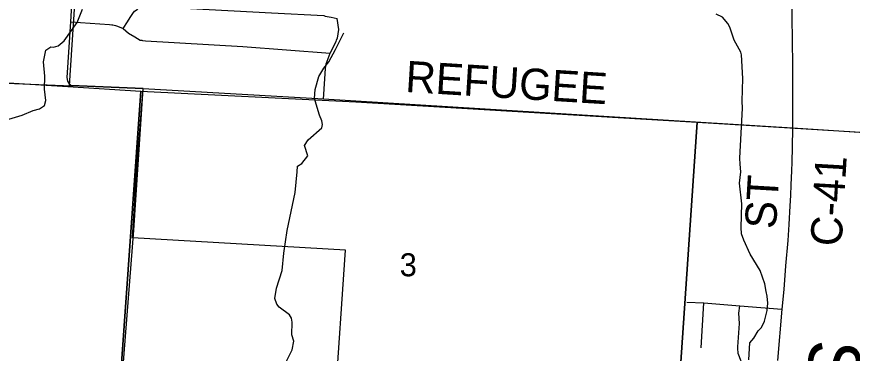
# Model space of a CAD drawing. Extents: x 0 to 34, y 0 to 26.1.
# Drawn here: x 26.701 to 28.22, y 20.153 to 20.765 of the extents above; entities that cross this region are included whole.
import ezdxf

# ---------------------------------------------------------------- set-up
doc = ezdxf.new("R2010")
doc.units = 0
for name, color, linetype in [('GM_X_City_Street', 7, 'Continuous'), ('GM_X_County_Road', 7, 'Continuous'), ('GM_X_County_Road_Text', 7, 'Continuous'), ('GM_X_Minor_River', 7, 'Continuous'), ('GM_X_Minor_River_Text', 7, 'Continuous'), ('GM_X_Section', 7, 'Continuous'), ('GM_X_Section_Text', 7, 'Continuous'), ('GM_X_Township_Road', 7, 'Continuous'), ('GM_X_Township_Road_Text', 7, 'Continuous'), ('SC_Scratch1', 7, 'Continuous')]:
    doc.layers.add(name, color=color, linetype=linetype)

msp = doc.modelspace()

# ---------------------------------------------------------------- linework, layer by layer
at = {"layer": 'GM_X_City_Street'}
for points in [[(26.8945, 20.7439), (26.902, 20.7562), (26.9069, 20.7638), (26.9121, 20.7711), (26.9152, 20.7752), (26.9197, 20.7787), (26.9227, 20.7814), (26.9258, 20.7829), (26.9307, 20.7852), (26.9356, 20.7867), (26.9424, 20.7871), (26.9516, 20.7872), (27.0169, 20.7802), (27.1642, 20.7721), (27.2591, 20.7676), (27.2618, 20.7665), (27.2728, 20.7646), (27.2834, 20.762)], [(26.7991, 20.7558), (26.8697, 20.7511), (26.8735, 20.7508), (26.8754, 20.7508), (26.8781, 20.75), (26.8807, 20.7496), (26.8842, 20.7481), (26.8945, 20.7439), (26.9038, 20.7351), (26.9153, 20.7284), (26.9253, 20.7229), (26.9283, 20.7225), (26.9298, 20.7221), (26.9348, 20.7214), (27.1121, 20.7108), (27.2707, 20.6992)], [(27.2587, 20.6151), (27.261, 20.652), (27.2622, 20.671), (27.2635, 20.6796), (27.2707, 20.6992), (27.2712, 20.7004), (27.2813, 20.7202), (27.2825, 20.7225), (27.284, 20.7267), (27.2847, 20.7301), (27.2854, 20.7343), (27.2862, 20.7419), (27.2834, 20.762)], [(26.6823, 20.6445), (26.8002, 20.6395)]]:
    msp.add_lwpolyline(points, dxfattribs=at)
at = {"layer": 'GM_X_County_Road'}
for points in [[(28.1081, 20.9), (28.1083, 20.8906), (28.1095, 20.8063), (28.11, 20.7606), (28.1105, 20.7257), (28.1113, 20.6737), (28.1112, 20.6162), (28.111, 20.5622)], [(28.111, 20.5622), (28.1107, 20.5278), (28.1099, 20.5008), (28.1095, 20.4847), (28.108, 20.4593), (28.1073, 20.4397), (28.1064, 20.421), (28.1045, 20.3872), (28.1026, 20.358), (28.0984, 20.3122), (28.0952, 20.2689), (28.0916, 20.233), (28.0838, 20.1395)]]:
    msp.add_lwpolyline(points, dxfattribs=at)
at = {"layer": 'GM_X_Minor_River'}
for points in [[(26.6868, 20.579), (26.7107, 20.5862), (26.7307, 20.5949), (26.7421, 20.5976), (26.7516, 20.604), (26.7535, 20.6127), (26.7527, 20.6234), (26.7516, 20.6332), (26.752, 20.6571), (26.7498, 20.6829), (26.7536, 20.7046), (26.7627, 20.7102), (26.768, 20.7099), (26.7759, 20.7121), (26.7869, 20.7216), (26.8108, 20.7546), (26.8203, 20.7789)], [(28.0319, 20.1409), (28.0338, 20.172), (28.0411, 20.1804), (28.0487, 20.1936), (28.0547, 20.1997), (28.0604, 20.2111), (28.0654, 20.2304), (28.0662, 20.2441), (28.0651, 20.2566), (28.0632, 20.2653), (28.0609, 20.279), (28.0523, 20.3037), (28.0342, 20.3333), (28.0225, 20.3584), (28.0187, 20.3702), (28.018, 20.3816), (28.0188, 20.4245), (28.0151, 20.4624), (28.0171, 20.4829), (28.0163, 20.497), (28.0156, 20.5076), (28.0203, 20.5987), (28.02, 20.6116), (28.0208, 20.653), (28.0182, 20.6958), (28.0171, 20.7008), (28.0054, 20.7224), (27.9971, 20.7464), (27.9937, 20.7532), (27.9839, 20.7642), (27.9722, 20.77)], [(27.1844, 20.1253), (27.2015, 20.1591), (27.2045, 20.1746), (27.2012, 20.1864), (27.2016, 20.2092), (27.2005, 20.2168), (27.1967, 20.2229), (27.1778, 20.2369), (27.1736, 20.2419), (27.1702, 20.2525), (27.1729, 20.2711), (27.1832, 20.3033), (27.1863, 20.3348), (27.1928, 20.3762), (27.207, 20.4456), (27.2105, 20.4832), (27.2112, 20.4931), (27.2192, 20.4984), (27.2298, 20.512), (27.2242, 20.531), (27.2307, 20.5412), (27.2553, 20.5628), (27.2565, 20.5689), (27.2557, 20.5757), (27.2516, 20.586), (27.2486, 20.5943), (27.2425, 20.6164), (27.2437, 20.6331), (27.2498, 20.6562), (27.2593, 20.6717), (27.2684, 20.6831), (27.2802, 20.7058), (27.2954, 20.7362)]]:
    msp.add_lwpolyline(points, dxfattribs=at)
at = {"layer": 'GM_X_Section'}
for points in [[(25.926, 20.6906), (26.2619, 20.6708), (26.7939, 20.6382), (26.9267, 20.63), (26.8884, 20.0918), (26.3915, 20.1255), (26.3885, 20.1257), (25.892, 20.1588)], [(26.9267, 20.63), (27.3172, 20.6101), (27.8347, 20.5796), (27.9376, 20.5735), (27.9001, 20.0205), (27.4021, 20.0547), (26.8884, 20.0918)], [(27.9376, 20.5735), (28.3638, 20.5476), (28.9502, 20.5089), (28.9104, 19.9472), (28.4191, 19.9828), (27.9001, 20.0205)]]:
    msp.add_lwpolyline(points, close=True, dxfattribs=at)
at = {"layer": 'GM_X_Township_Road'}
for p, q in [((26.9307, 20.6339), (26.8002, 20.6395)), ((27.9451, 20.1628), (27.9502, 20.2444))]:
    msp.add_line(p, q, dxfattribs=at)
for points in [[(26.8002, 20.6395), (26.7966, 20.6429), (26.7937, 20.6477), (26.7927, 20.6547), (26.7991, 20.7558), (26.8075, 20.9)], [(26.8913, 20.0905), (26.9136, 20.3771), (26.9307, 20.6339)], [(28.111, 20.5622), (27.2587, 20.6151), (26.9307, 20.6339)], [(29.9005, 20.446), (29.3177, 20.4844), (28.111, 20.5622)], [(27.9189, 20.2461), (27.9502, 20.2444), (28.0154, 20.2392), (28.0916, 20.233)], [(28.0186, 20.0892), (28.021, 20.1217), (28.0201, 20.1316), (28.0167, 20.1416), (28.0136, 20.1492), (28.0126, 20.1524), (28.0122, 20.1553), (28.0118, 20.1592), (28.0119, 20.1643), (28.0126, 20.1731), (28.015, 20.207), (28.0137, 20.2257), (28.0154, 20.2392)]]:
    msp.add_lwpolyline(points, dxfattribs=at)
at = {"layer": 'SC_Scratch1'}
msp.add_lwpolyline([(26.6845, 20.1077), (26.701, 20.1065), (26.7245, 20.1049), (26.7427, 20.1036), (26.8876, 20.0933), (26.8945, 20.0928), (26.8785, 19.8436), (26.9125, 19.8413), (26.974, 19.8369), (26.9835, 19.8365), (27.0408, 19.8326), (27.0849, 19.8296), (27.0944, 19.8286), (27.1249, 19.8269), (27.3818, 19.8095), (27.3992, 20.0574), (27.2799, 20.0653), (27.2988, 20.3406), (26.9112, 20.3627), (26.9194, 20.4905), (26.9305, 20.6345), (26.8, 20.64), (26.7968, 20.64), (26.8139, 20.9)], dxfattribs=at)

# ---------------------------------------------------------------- texts
at = {"layer": 'GM_X_County_Road_Text'}
for s, rotation, p in [('C-41', 86.6637, (28.2003, 20.3464)), ('ST', 86.604, (28.0811, 20.3781))]:
    msp.add_text(s, height=0.05682, rotation=rotation, dxfattribs=at).set_placement(p)
at = {"layer": 'GM_X_Minor_River_Text'}
msp.add_text('Sycamore', height=0.09469, rotation=268.0002, dxfattribs=at).set_placement((28.1417, 20.1785))
at = {"layer": 'GM_X_Section_Text'}
msp.add_text('3', height=0.0419, rotation=0, dxfattribs=at).set_placement((27.3971, 20.2929))
at = {"layer": 'GM_X_Township_Road_Text'}
msp.add_text('REFUGEE', height=0.05682, rotation=356.4805, dxfattribs=at).set_placement((27.4064, 20.6285))

doc.saveas('drawing.dxf')
